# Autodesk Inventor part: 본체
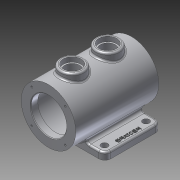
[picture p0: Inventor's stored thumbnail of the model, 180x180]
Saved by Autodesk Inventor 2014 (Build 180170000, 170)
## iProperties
Created: 2014-12
Part Number: 본체
Material: 알루미늄 6061
Document SubType Name: Modeling
Designer: Owner
Mass: 1294.01 g
Surface Area: 1040.13 cm^2
Volume: 477.494 cm^3
Density: 2.71 g/cm^3
Appearance: 알루미늄 - 평지
Author: Owner
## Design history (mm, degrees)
sketch "스케치1"
  geometry: C1 r 46 at (0, 0); 1 further point
  constraints: 1 centre point, 1 coincident
  dimensions: "d0" = 92 diameter of C1
extrude "돌출1" new body sketch "스케치1" stored distance "d1" = 140; taper "d2" = 0 deg
sketch "스케치2"
  geometry: C1 r 46 at (0, 0) reference; C2 r 30 at (0, 0)
  constraints: 1 centre point, 1 coincident
  dimensions: "d3" = 60 diameter of C2
extrude "돌출2" cut sketch "스케치2" distance "d4" = 12; taper "d5" = 0 deg
sketch "스케치3"
  geometry: C1 r 30 at (0, 0) reference; C2 r 37.5 at (0, 0)
  constraints: 1 centre point, 1 coincident
  dimensions: "d6" = 75 diameter of C2
extrude "돌출3" cut sketch "스케치3" distance "d7" = 116; taper "d8" = 0 deg
sketch "스케치4"
  geometry: C1 r 46 at (0, 0) reference; C2 r 30 at (0, 0)
  constraints: 1 centre point, 1 coincident
  dimensions: "d9" = 60 diameter of C2
extrude "돌출4" cut sketch "스케치4" distance "d10" = 12; taper "d11" = 0 deg
node "작업 평면1"
sketch "스케치5"
  geometry: L1 (46, 70)-(-46, 70) reference; L2 (-46, -70)-(46, -70) reference; C1 r 20 at (0, 30); C2 r 20 at (0, -30); 1 further point
  constraints: 2 centre point, 2 vertical alignment, 1 equal radius
  dimensions: "d13" = 40 diameter of C1; "d14" = 40 distance from line of C1.centre L1; "d15" = 40 distance from line of C2.centre L2
extrude "돌출5" join sketch "스케치5" stored distance "d16" = 12; taper "d17" = 0 deg
hole "구멍1" diameter "d20" = 25; stored, may be unused: countersink angle "d24" = 90 deg, drill point angle "d26" = 118 deg; dims "d18" = 10, "d19" = 10, "d21" = 6, "d22" = 30, "d23" = 8, "d25" = 8
sketch "스케치7"
  geometry: L1 (0, 0)-(28.284, 28.284); L2 (0, 0)-(40, 0); C1 r 46 at (0, 0) reference; 1 further point
  constraints: 4 end point, 1 coincident, 1 equal length, 1 horizontal
  dimensions: "d27" = 40 distance of L1.start L1.end; "d28" = 45 deg angle of L2 L1
hole "구멍2" sketch "스케치7" at (28.284, 28.284) diameter "d29" = 3.242; stored, may be unused: countersink angle "d33" = 90 deg, drill point angle "d35" = 118 deg; dims "d30" = 8, "d31" = 1, "d32" = 8, "d34" = 10
node "작업 평면2"
sketch "스케치8"
  geometry: L1 (-65, 55)-(65, 55); L2 (65, 55)-(65, -40); L3 (65, -40)-(-65, -40); L4 (-65, -40)-(-65, 55); L5 (46, 70)-(-46, 70) reference; 2 further points
  constraints: 8 end point, 2 parallel, 1 horizontal, 1 midpoint, 1 perpendicular, 1 vertical alignment
  dimensions: "d40" = 130 distance of L1.start L1.end; "d41" = 95 distance of L1.end L2.end; "d43" = 15 distance between parallel lines of L1 L5
extrude "돌출6" join sketch "스케치8" distance "d44" = 12; taper "d45" = 0 deg
sketch "스케치10"
  geometry: L1 (-25.923, 55)-(-65, 55) reference; L2 (-65, 55)-(-65, -40) reference; C1 r 5.5 at (-52, 42.5); 1 further point
  constraints: 1 centre point
  dimensions: "d47" = 11 diameter of C1; "d48" = 12.5 distance from line of C1.centre L1; "d49" = 13 distance from line of C1.centre L2
extrude "돌출7" cut sketch "스케치10" stored distance "d50" = 12; taper "d51" = 0 deg
sketch "스케치11"
  geometry: L1 (-65, 55)-(-65, -40) reference; C1 r 5.5 at (-52, 42.5) reference; C2 r 5.5 at (-52, -27.5); 1 further point
  constraints: 1 centre point
  dimensions: "d52" = 11 diameter of C2; "d53" = 13 distance from line of C2.centre L1; "d54" = 70 distance of C2.centre C1.centre
extrude "돌출8" cut sketch "스케치11" distance "d55" = 12; taper "d56" = 0 deg
sketch "스케치9" dims "d35" = 118 deg
  geometry: L1 (65, -40)-(65, 55) reference; C1 r 5.5 at (52, 42.5) reference; 2 further points
  constraints: 1 other
  dimensions: "d46" = 8 distance from line of L1 point (57, 7.5); "d57" = 35 vertical distance of point (57, 7.5) C1.centre
feature "엠보싱1" sketch "스케치9" dims "d2" = 0, "d10" = 12, "d58" = 1, "d59" = 0
fillet "모깎기1" dims "d60" = 3
fillet "모깎기2" dims "d61" = 5
fillet "모깎기3" dims "d62" = 3
fillet "모깎기4" dims "d63" = 3
fillet "모깎기5" dims "d64" = 10
fillet "모깎기6" dims "d65" = 3
chamfer "모따기1" distance "d66" = 1; stored, may be unused: second distance "d67" = 2, angle "d68" = 45 deg
fillet "모깎기7" dims "d69" = 3
node "솔리드1"
mirror "대칭1"
pattern_circular "원형 패턴1" dims angle "d37" = 360 deg
mirror "대칭2"
mirror "대칭3"
other parameters: "d12" = 56
